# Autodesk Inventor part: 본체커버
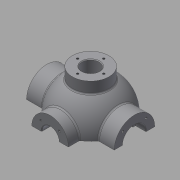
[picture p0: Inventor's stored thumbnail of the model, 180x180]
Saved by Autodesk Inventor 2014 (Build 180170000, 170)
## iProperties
Created: 2015-12
Part Number: 본체커버
Material: 알루미늄 6061
Document SubType Name: Modeling
Designer: mduedu
Density: 2.71 g/cm^3
Mass: 574.083 g
Surface Area: 451.737 cm^2
Volume: 211.839 cm^3
Appearance: 알루미늄 - 평지
Author: mduedu
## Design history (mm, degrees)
sketch "스케치1"
  geometry: L1 (-53, 0)-(53, 0); A1 r 53 centre (0, 0) between (53, 0) and (-53, 0); 2 further points
  constraints: 2 coincident, 2 end point, 2 point on circle, 1 centre point, 1 horizontal, 1 midpoint
  dimensions: "d0" = 53 radius of A1
revolve "회전1" sketch "스케치1" stored, may be unused: angle "d2" = 90 deg
feature "쉘1" dims "d11" = 10
node "작업 평면1"
sketch "스케치2"
  geometry: C1 r 31 at (0, 0); 1 further point
  constraints: 1 centre point, 1 coincident
  dimensions: "d4" = 62 diameter of C1
extrude "돌출1" join sketch "스케치2" stored distance "d5" = 10; taper "d6" = 0 deg
node "작업 평면2"
sketch "스케치3"
  geometry: C1 r 28 at (0, 0); 1 further point
  constraints: 1 centre point, 1 coincident
  dimensions: "d8" = 56 diameter of C1
extrude "돌출2" join sketch "스케치3" stored distance "d9" = 10; taper "d10" = 0 deg
hole "구멍1" diameter "d14" = 35; stored, may be unused: countersink angle "d18" = 90 deg, drill point angle "d20" = 0 deg; dims "d12" = 10, "d13" = 10, "d15" = 6, "d16" = 4, "d17" = 2, "d19" = 16
hole "구멍2" diameter "d23" = 27; stored, may be unused: countersink angle "d27" = 90 deg, drill point angle "d29" = 0 deg; dims "d21" = 10, "d22" = 10, "d24" = 6, "d25" = 4, "d26" = 2, "d28" = 16
fillet "모깎기1" dims "d30" = 0.3
hole "구멍3" diameter "d33" = 26; stored, may be unused: countersink angle "d37" = 90 deg, drill point angle "d39" = 0 deg; dims "d31" = 10, "d32" = 10, "d34" = 6, "d35" = 4, "d36" = 2, "d38" = 16
chamfer "모따기1" distance "d40" = 1; stored, may be unused: second distance "d41" = 2, angle "d42" = 45 deg
sketch "스케치4"
  geometry: L1 (0, 0)-(0, -25); L2 (0, 0)-(-17.678, -17.678); A1 r 25 centre (0, 0) between (-17.678, -17.678) and (0, -25); 1 further point
  constraints: 4 end point, 2 point on circle, 1 centre point, 1 coincident, 1 vertical
  dimensions: "d43" = 50 diameter of A1; "d47" = 45 deg angle of L1 L2
hole "구멍4" sketch "스케치4" at (-17.678, -17.678) diameter "d49" = 3.242; stored, may be unused: countersink angle "d53" = 90 deg, drill point angle "d55" = 118 deg; dims "d50" = 11, "d51" = 4, "d52" = 2, "d54" = 13
sketch "스케치5"
  geometry: L1 (0, 0)-(0, -20); L2 (0, 0)-(-14.142, -14.142); A1 r 20 centre (0, 0) between (0, -20) and (-14.142, -14.142); 2 further points
  constraints: 4 end point, 2 coincident, 2 point on circle, 1 centre point, 1 vertical
  dimensions: "d59" = 40 diameter of A1; "d65" = 45 deg angle of L1 L2
hole "구멍5" sketch "스케치5" at (-14.142, -14.142) diameter "d67" = 3.242; stored, may be unused: countersink angle "d71" = 90 deg, drill point angle "d73" = 118 deg; dims "d68" = 8, "d69" = 4, "d70" = 2, "d72" = 10
node "작업 평면3"
sketch "스케치6"
  geometry: C1 r 65 at (0, 0); 1 further point
  constraints: 1 centre point, 1 coincident
  dimensions: "d78" = 130 diameter of C1
extrude "돌출3" join sketch "스케치6" distance "d80" = 10; taper "d81" = 0 deg
sketch "스케치7"
  geometry: C1 r 20 at (0, 0); 1 further point
  constraints: 1 centre point, 1 coincident
  dimensions: "d82" = 40 diameter of C1
extrude "돌출4" join sketch "스케치7" stored distance "d84" = 10; taper "d85" = 0 deg
sketch "스케치8"
  geometry: 2 further points
  constraints: 1 coincident
hole "구멍6" sketch "스케치8" at (0, 0) diameter "d86" = 20; stored, may be unused: countersink angle "d90" = 90 deg, drill point angle "d92" = 118 deg; dims "d87" = 7, "d88" = 40, "d89" = 5, "d91" = 10
fillet "모깎기2" dims "d93" = 0.3
sketch "스케치9"
  geometry: L1 (65, -75)-(-65, -75) reference; L2 (-45, -75)-(-38.245, -36.692); A1 r 53 centre (0, 0) between (42.988, 31) and (42.988, -31) reference; 1 further point
  constraints: 2 end point, 1 point on circle, 1 point on line
  dimensions: "d94" = 45 horizontal distance of L2.start point (0, 0); "d95" = 80 deg angle of L2 L1
feature "리브1" sketch "스케치9" dims "d96" = 1, "d97" = 8, "d98" = 0, "d99" = 0, "d100" = 1, "d101" = 1
sketch "스케치10"
  geometry: L1 (0, 0)-(0, -55); L2 (0, 0)-(-38.891, -38.891); A1 r 55 centre (0, 0) between (0, -55) and (-38.891, -38.891); 2 further points
  constraints: 4 end point, 2 coincident, 2 point on circle, 1 centre point, 1 vertical
  dimensions: "d105" = 110 diameter of A1; "d107" = 45 deg angle of L1 L2
hole "구멍7" sketch "스케치10" at (-38.891, -38.891) diameter "d109" = 10; stored, may be unused: countersink angle "d113" = 90 deg, drill point angle "d115" = 118 deg; dims "d110" = 7, "d111" = 40, "d112" = 5, "d114" = 10
fillet "모깎기3" dims "d120" = 3
fillet "모깎기4" dims "d121" = 3, "d122" = 3
fillet "모깎기5" dims "d123" = 3
fillet "모깎기6" dims "d124" = 3
sketch "스케치11"
  geometry: C1 r 5 at (-38.891, 38.891) reference; C2 r 5 at (38.891, 38.891) reference; C3 r 5 at (38.891, -38.891) reference; C4 r 5 at (-38.891, -38.891) reference; C5 r 20 at (0, 0) reference; C6 r 65 at (0, 0) reference; 1 further point
  constraints: 3 other
feature "엠보싱1" sketch "스케치11" dims "d125" = 0.5, "d126" = 0
sketch "스케치12"
  geometry: L1 (0, 100)-(0, -100); L2 (0, 100)-(-150, 100); L3 (-150, 100)-(-150, -100); L4 (-150, -100)-(0, -100); 2 further points
  constraints: 8 end point, 3 perpendicular, 1 coincident, 1 midpoint, 1 vertical
  dimensions: "d127" = 200 distance of L2.end L3.end; "d129" = 150 distance of L3.end L1.end
extrude "돌출5" cut sketch "스케치12" stored distance "d130" = 10; taper "d131" = 0 deg
sketch "스케치13"
  geometry: C1 r 7 at (0, -53); A1 r 53 centre (0, 0) between (-42.113, -32.179) and (42.113, -32.179) reference; 1 further point
  constraints: 1 centre point, 1 point on circle
  dimensions: "d132" = 14 diameter of C1
extrude "돌출6" join sketch "스케치13" distance "d133" = 5; taper "d134" = 0 deg
sketch "스케치14"
  geometry: C1 r 7 at (0, 0) reference; 1 further point
extrude "돌출7" cut sketch "스케치14" stored distance "d135" = 5; taper "d136" = 0 deg
sketch "스케치15"
  geometry: C1 r 2.25 at (0, 53); A1 r 7 centre (0, 53) between (6.965, 52.302) and (-6.965, 52.302) reference; 1 further point
  constraints: 1 centre point, 1 coincident
  dimensions: "d139" = 4.5 diameter of C1
extrude "돌출8" cut sketch "스케치15" stored distance "d141" = 5; taper "d142" = 0 deg
fillet "모깎기7" dims "d143" = 3
fillet "모깎기8" dims "d144" = 1
fillet "모깎기9" dims "d145" = 1
fillet "모깎기10" dims "d146" = 1
node "작업 평면4"
sketch "스케치16"
  geometry: C1 r 28 at (0, 0); 1 further point
  constraints: 1 centre point, 1 coincident
  dimensions: "d148" = 56 diameter of C1
extrude "돌출9" join sketch "스케치16" stored distance "d150" = 5; taper "d151" = 0 deg
hole "구멍8" diameter "d154" = 26; stored, may be unused: countersink angle "d158" = 90 deg, drill point angle "d160" = 118 deg; dims "d152" = 10, "d153" = 10, "d155" = 6, "d156" = 4, "d157" = 2, "d159" = 8
sketch "스케치17" dims "d161" = 40
  geometry: 3 further points
  constraints: 2 vertical alignment, 1 coincident, 2 other
hole "구멍9" sketch "스케치17" at (0, 20) diameter "d163" = 3.242; stored, may be unused: countersink angle "d167" = 90 deg, drill point angle "d169" = 118 deg; dims "d164" = 8, "d165" = 4, "d166" = 2, "d168" = 10
fillet "모깎기11" dims "d173" = 3
chamfer "모따기2" distance "d174" = 1; stored, may be unused: second distance "d175" = 2, angle "d176" = 45 deg
node "솔리드1"
mirror "대칭1"
mirror "대칭2"
pattern_circular "원형 패턴1" dims angle "d57" = 360 deg
mirror "대칭3"
pattern_circular "원형 패턴2" dims angle "d75" = 360 deg
pattern_circular "원형 패턴3" dims angle "d103" = 360 deg
pattern_circular "원형 패턴4" dims angle "d118" = 360 deg
pattern_circular "원형 패턴5" dims angle "d171" = 360 deg
node "투영된 루프1"
other parameters: "d3" = 67, "d7" = 62, "d77" = -85, "d147" = 62
